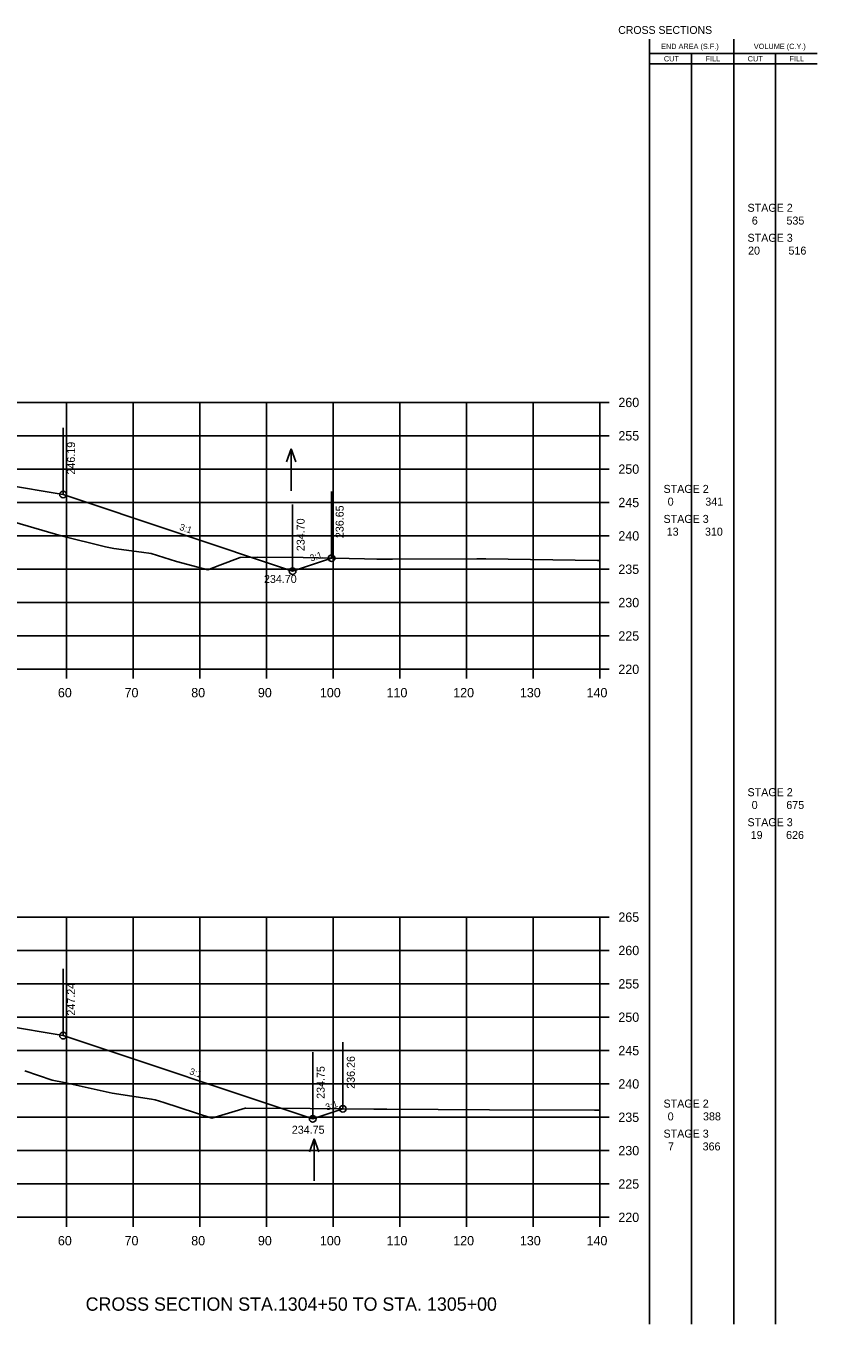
# Model space of a CAD drawing. Extents: x 1342547 to 1344156, y -1532351 to -1517216.
# Drawn here: x 1342756.8 to 1342875.5, y -1518906.9 to -1518712.3 of the extents above; entities that cross this region are included whole.
import ezdxf

# ---------------------------------------------------------------- set-up
doc = ezdxf.new("R2010")
doc.units = 0
for name, color, linetype in [('Level 2', 7, 'Continuous'), ('R_Axis', 7, 'Continuous'), ('R_Axis Annot', 7, 'Continuous'), ('R_Border Notes', 7, 'Continuous'), ('R_Draft', 7, 'Continuous'), ('R_Exist Surface', 7, 'Continuous'), ('R_Fin Surface', 7, 'Continuous'), ('R_Grid', 7, 'Continuous'), ('R_No Plot', 7, 'Continuous'), ('R_Water', 7, 'Continuous'), ('R_Xsect Elev', 7, 'Continuous'), ('R_Xsect Slope', 7, 'Continuous')]:
    doc.layers.add(name, color=color, linetype=linetype)

msp = doc.modelspace()

# ---------------------------------------------------------------- linework, layer by layer
at = {"layer": 'Level 2'}
for p, q in [((1342850.33, -1518906.86), (1342850.32, -1518714.25)), ((1342862.99, -1518906.86), (1342862.99, -1518714.25)), ((1342850.32, -1518716.41), (1342863.59, -1518716.41)), ((1342856.66, -1518906.86), (1342856.66, -1518716.41)), ((1342863.59, -1518716.41), (1342875.48, -1518716.41)), ((1342869.23, -1518906.86), (1342869.23, -1518716.41)), ((1342850.32, -1518717.97), (1342863.59, -1518717.97)), ((1342863.59, -1518717.97), (1342875.48, -1518717.97))]:
    msp.add_line(p, q, dxfattribs=at)
at = {"layer": 'R_Axis'}
for p, q in [((1342842.87, -1518808.71), (1342842.87, -1518768.71)), ((1342844.27, -1518768.71), (1342842.87, -1518768.71)), ((1342844.27, -1518773.71), (1342842.87, -1518773.71)), ((1342844.27, -1518778.71), (1342842.87, -1518778.71)), ((1342844.27, -1518783.71), (1342842.87, -1518783.71)), ((1342844.27, -1518788.71), (1342842.87, -1518788.71)), ((1342844.27, -1518793.71), (1342842.87, -1518793.71)), ((1342844.27, -1518798.71), (1342842.87, -1518798.71)), ((1342844.27, -1518803.71), (1342842.87, -1518803.71)), ((1342562.87, -1518808.71), (1342842.87, -1518808.71)), ((1342762.87, -1518810.11), (1342762.87, -1518808.71)), ((1342772.87, -1518810.11), (1342772.87, -1518808.71)), ((1342782.87, -1518810.11), (1342782.87, -1518808.71)), ((1342792.87, -1518810.11), (1342792.87, -1518808.71)), ((1342802.87, -1518810.11), (1342802.87, -1518808.71)), ((1342812.87, -1518810.11), (1342812.87, -1518808.71)), ((1342822.87, -1518810.11), (1342822.87, -1518808.71)), ((1342832.87, -1518810.11), (1342832.87, -1518808.71)), ((1342842.87, -1518810.11), (1342842.87, -1518808.71)), ((1342844.27, -1518808.71), (1342842.87, -1518808.71)), ((1342842.87, -1518890.86), (1342842.87, -1518845.86)), ((1342844.27, -1518845.86), (1342842.87, -1518845.86)), ((1342844.27, -1518850.86), (1342842.87, -1518850.86)), ((1342844.27, -1518855.86), (1342842.87, -1518855.86)), ((1342844.27, -1518860.86), (1342842.87, -1518860.86)), ((1342844.27, -1518865.86), (1342842.87, -1518865.86)), ((1342844.27, -1518870.86), (1342842.87, -1518870.86)), ((1342844.27, -1518875.86), (1342842.87, -1518875.86)), ((1342844.27, -1518880.86), (1342842.87, -1518880.86)), ((1342844.27, -1518885.86), (1342842.87, -1518885.86)), ((1342562.87, -1518890.86), (1342842.87, -1518890.86)), ((1342762.87, -1518892.26), (1342762.87, -1518890.86)), ((1342772.87, -1518892.26), (1342772.87, -1518890.86)), ((1342782.87, -1518892.26), (1342782.87, -1518890.86)), ((1342792.87, -1518892.26), (1342792.87, -1518890.86)), ((1342802.87, -1518892.26), (1342802.87, -1518890.86)), ((1342812.87, -1518892.26), (1342812.87, -1518890.86)), ((1342822.87, -1518892.26), (1342822.87, -1518890.86)), ((1342832.87, -1518892.26), (1342832.87, -1518890.86)), ((1342842.87, -1518892.26), (1342842.87, -1518890.86)), ((1342844.27, -1518890.86), (1342842.87, -1518890.86))]:
    msp.add_line(p, q, dxfattribs=at)
at = {"layer": 'R_Exist Surface'}
for points in [[(1342755.11, -1518786.64), (1342762.08, -1518788.69), (1342768.75, -1518790.33), (1342769.98, -1518790.59), (1342774.12, -1518791.16), (1342775.59, -1518791.37), (1342779.37, -1518792.57), (1342784.1, -1518793.78), (1342785.88, -1518793.09), (1342788.95, -1518791.93), (1342791.61, -1518791.92), (1342798.39, -1518791.96), (1342807.57, -1518792.16), (1342809.45, -1518792.21), (1342811.79, -1518792.19), (1342824.43, -1518792.14), (1342825.77, -1518792.15), (1342842.52, -1518792.38), (1342842.87, -1518792.38)], [(1342756.64, -1518868.92), (1342760.76, -1518870.32), (1342762.55, -1518870.67), (1342769.74, -1518872.24), (1342775.63, -1518873.15), (1342776.18, -1518873.26), (1342777.5, -1518873.67), (1342784.7, -1518875.99), (1342789.68, -1518874.5), (1342789.71, -1518874.49), (1342789.78, -1518874.49), (1342799.43, -1518874.54), (1342808.98, -1518874.65), (1342809.97, -1518874.66), (1342810.94, -1518874.66), (1342826.36, -1518874.76), (1342842.07, -1518874.81), (1342842.87, -1518874.82)]]:
    msp.add_lwpolyline(points, dxfattribs=at)
at = {"layer": 'R_Fin Surface'}
for points in [[(1342629.64, -1518792.54), (1342630.13, -1518792.71), (1342643.37, -1518788.3), (1342650.5, -1518787.11), (1342665.37, -1518784.63), (1342671.37, -1518784.17), (1342673.37, -1518784.01), (1342702.87, -1518781.74), (1342732.37, -1518779.47), (1342734.37, -1518779.32), (1342740.37, -1518778.85), (1342753.42, -1518781.03), (1342762.37, -1518782.52), (1342796.81, -1518794), (1342802.66, -1518792.05)], [(1342627, -1518874.19), (1342627.98, -1518874.52), (1342643.37, -1518869.39), (1342650.5, -1518868.21), (1342665.37, -1518865.73), (1342671.37, -1518865.27), (1342673.37, -1518865.11), (1342702.87, -1518862.84), (1342732.37, -1518860.57), (1342734.37, -1518860.41), (1342740.37, -1518859.95), (1342753.42, -1518862.13), (1342762.37, -1518863.62), (1342799.82, -1518876.1), (1342804.34, -1518874.59)]]:
    msp.add_lwpolyline(points, dxfattribs=at)
at = {"layer": 'R_Grid'}
for p, q in [((1342562.87, -1518768.71), (1342842.87, -1518768.71)), ((1342762.87, -1518808.71), (1342762.87, -1518768.71)), ((1342772.87, -1518808.71), (1342772.87, -1518768.71)), ((1342782.87, -1518808.71), (1342782.87, -1518768.71)), ((1342792.87, -1518808.71), (1342792.87, -1518768.71)), ((1342802.87, -1518808.71), (1342802.87, -1518768.71)), ((1342812.87, -1518808.71), (1342812.87, -1518768.71)), ((1342822.87, -1518808.71), (1342822.87, -1518768.71)), ((1342832.87, -1518808.71), (1342832.87, -1518768.71)), ((1342842.87, -1518808.71), (1342842.87, -1518768.71)), ((1342562.87, -1518773.71), (1342842.87, -1518773.71)), ((1342562.87, -1518778.71), (1342842.87, -1518778.71)), ((1342562.87, -1518783.71), (1342842.87, -1518783.71)), ((1342562.87, -1518788.71), (1342842.87, -1518788.71)), ((1342562.87, -1518793.71), (1342842.87, -1518793.71)), ((1342562.87, -1518798.71), (1342842.87, -1518798.71)), ((1342562.87, -1518803.71), (1342842.87, -1518803.71)), ((1342562.87, -1518808.71), (1342842.87, -1518808.71)), ((1342562.87, -1518845.86), (1342842.87, -1518845.86)), ((1342762.87, -1518890.86), (1342762.87, -1518845.86)), ((1342772.87, -1518890.86), (1342772.87, -1518845.86)), ((1342782.87, -1518890.86), (1342782.87, -1518845.86)), ((1342792.87, -1518890.86), (1342792.87, -1518845.86)), ((1342802.87, -1518890.86), (1342802.87, -1518845.86)), ((1342812.87, -1518890.86), (1342812.87, -1518845.86)), ((1342822.87, -1518890.86), (1342822.87, -1518845.86)), ((1342832.87, -1518890.86), (1342832.87, -1518845.86)), ((1342842.87, -1518890.86), (1342842.87, -1518845.86)), ((1342562.87, -1518850.86), (1342842.87, -1518850.86)), ((1342562.87, -1518855.86), (1342842.87, -1518855.86)), ((1342562.87, -1518860.86), (1342842.87, -1518860.86)), ((1342562.87, -1518865.86), (1342842.87, -1518865.86)), ((1342562.87, -1518870.86), (1342842.87, -1518870.86)), ((1342562.87, -1518875.86), (1342842.87, -1518875.86)), ((1342562.87, -1518880.86), (1342842.87, -1518880.86)), ((1342562.87, -1518885.86), (1342842.87, -1518885.86)), ((1342562.87, -1518890.86), (1342842.87, -1518890.86))]:
    msp.add_line(p, q, dxfattribs=at)
at = {"layer": 'R_No Plot'}
for centre in [(1342762.37, -1518782.52), (1342802.66, -1518792.05), (1342796.81, -1518794), (1342762.37, -1518863.62), (1342804.34, -1518874.59), (1342799.82, -1518876.1)]:
    msp.add_circle(centre, 0.5, dxfattribs=at)
at = {"layer": 'R_Water'}
for p, q in [((1342796.61, -1518775.67), (1342795.91, -1518777.59)), ((1342796.61, -1518781.95), (1342796.61, -1518775.67)), ((1342796.61, -1518775.67), (1342797.31, -1518777.59)), ((1342800.02, -1518879.11), (1342799.32, -1518881.03)), ((1342800.02, -1518885.4), (1342800.02, -1518879.11)), ((1342800.02, -1518879.11), (1342800.72, -1518881.03))]:
    msp.add_line(p, q, dxfattribs=at)
at = {"layer": 'R_Xsect Elev'}
for p, q in [((1342762.37, -1518782.52), (1342762.37, -1518772.52)), ((1342802.66, -1518792.05), (1342802.66, -1518782.05)), ((1342796.81, -1518794), (1342796.81, -1518784)), ((1342762.37, -1518863.62), (1342762.37, -1518853.62)), ((1342804.34, -1518874.59), (1342804.34, -1518864.59)), ((1342799.82, -1518876.1), (1342799.82, -1518866.1))]:
    msp.add_line(p, q, dxfattribs=at)

# ---------------------------------------------------------------- texts
at = {"layer": 'Level 2'}
for s, height, p in [('END AREA (S.F.)', 0.7937, (1342852.08, -1518715.73)), ('VOLUME (C.Y.)', 0.7937, (1342865.99, -1518715.73)), ('CUT', 0.794, (1342852.5, -1518717.59)), ('FILL', 0.794, (1342858.76, -1518717.59)), ('CUT', 0.794, (1342865.07, -1518717.59)), ('FILL', 0.794, (1342871.33, -1518717.59)), (' STAGE 2 ', 1.2, (1342864.6, -1518740.13)), ('6', 1.2, (1342865.69, -1518742.05)), ('535', 1.2, (1342870.89, -1518742.05)), (' STAGE 3 ', 1.2, (1342864.6, -1518744.63)), ('20', 1.2, (1342865.13, -1518746.55)), ('516', 1.2, (1342871.19, -1518746.55)), (' STAGE 2 ', 1.2, (1342852, -1518782.27)), ('0', 1.2, (1342853.07, -1518784.18)), ('341', 1.2, (1342858.71, -1518784.18)), (' STAGE 3 ', 1.2, (1342852, -1518786.77)), ('13', 1.2, (1342852.92, -1518788.68)), ('310', 1.2, (1342858.66, -1518788.68)), (' STAGE 2 ', 1.2, (1342864.6, -1518827.73)), ('0', 1.2, (1342865.67, -1518829.65)), ('675', 1.2, (1342870.86, -1518829.65)), (' STAGE 3 ', 1.2, (1342864.6, -1518832.23)), ('19', 1.2, (1342865.52, -1518834.15)), ('626', 1.2, (1342870.83, -1518834.15)), (' STAGE 2 ', 1.2, (1342852, -1518874.41)), ('0', 1.2, (1342853.07, -1518876.33)), ('388', 1.2, (1342858.37, -1518876.33)), (' STAGE 3 ', 1.2, (1342852, -1518878.91)), ('7', 1.2, (1342853.12, -1518880.83)), ('366', 1.2, (1342858.31, -1518880.83))]:
    msp.add_text(s, height=height, dxfattribs=at).set_placement(p)
at = {"layer": 'R_Axis Annot'}
for s, p in [('260', (1342845.67, -1518769.41)), ('255', (1342845.67, -1518774.41)), ('250', (1342845.67, -1518779.41)), ('245', (1342845.67, -1518784.41)), ('240', (1342845.67, -1518789.41)), ('235', (1342845.67, -1518794.41)), ('230', (1342845.67, -1518799.41)), ('225', (1342845.67, -1518804.41)), ('220', (1342845.67, -1518809.41)), ('60', (1342761.6, -1518812.91)), ('70', (1342771.6, -1518812.91)), ('80', (1342781.6, -1518812.91)), ('90', (1342791.6, -1518812.91)), ('100', (1342800.9, -1518812.91)), ('110', (1342810.9, -1518812.91)), ('120', (1342820.9, -1518812.91)), ('130', (1342830.9, -1518812.91)), ('140', (1342840.9, -1518812.91)), ('265', (1342845.67, -1518846.56)), ('260', (1342845.67, -1518851.56)), ('255', (1342845.67, -1518856.56)), ('250', (1342845.67, -1518861.56)), ('245', (1342845.67, -1518866.56)), ('240', (1342845.67, -1518871.56)), ('235', (1342845.67, -1518876.56)), ('230', (1342845.67, -1518881.56)), ('225', (1342845.67, -1518886.56)), ('220', (1342845.67, -1518891.56)), ('60', (1342761.6, -1518895.06)), ('70', (1342771.6, -1518895.06)), ('80', (1342781.6, -1518895.06)), ('90', (1342791.6, -1518895.06)), ('100', (1342800.9, -1518895.06)), ('110', (1342810.9, -1518895.06)), ('120', (1342820.9, -1518895.06)), ('130', (1342830.9, -1518895.06)), ('140', (1342840.9, -1518895.06))]:
    msp.add_text(s, height=1.4, dxfattribs=at).set_placement(p)
at = {"layer": 'R_Border Notes'}
msp.add_text('CROSS SECTIONS', height=1.1775, dxfattribs=at).set_placement((1342845.65, -1518713.47))
at = {"layer": 'R_Draft'}
msp.add_text('CROSS SECTION STA.1304+50 TO STA. 1305+00', height=2, dxfattribs=at).set_placement((1342765.76, -1518904.86))
at = {"layer": 'R_Xsect Elev'}
for s, p in [('246.19', (1342764.17, -1518779.52)), ('236.65', (1342804.46, -1518789.05)), ('234.70', (1342798.61, -1518791)), ('247.24', (1342764.17, -1518860.62)), ('236.26', (1342806.14, -1518871.59)), ('234.75', (1342801.62, -1518873.1))]:
    msp.add_text(s, height=1.2, rotation=90, dxfattribs=at).set_placement(p)
for s, p in [('234.70', (1342792.51, -1518795.77)), ('234.75', (1342796.69, -1518878.33))]:
    msp.add_text(s, height=1.2, dxfattribs=at).set_placement(p)
at = {"layer": 'R_Xsect Slope'}
for rotation, p in [(341.5651, (1342779.75, -1518787.79)), (18.4349, (1342799.58, -1518792.56)), (341.5651, (1342781.25, -1518869.39)), (18.4349, (1342801.92, -1518874.87))]:
    msp.add_text('3:1', height=1, rotation=rotation, dxfattribs=at).set_placement(p)

doc.saveas('drawing.dxf')
